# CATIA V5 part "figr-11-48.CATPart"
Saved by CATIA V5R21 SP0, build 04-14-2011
Part number: Part1
Bounding box of the stored display mesh (mm): x -270.607 to 0, y -223.278 to 0, z -13.562 to 46.691
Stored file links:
  D:\CATIA V5R21 E-RESOURCES\CATIA-V5R21\catia-v5r21-prt\c11-catia-v5r21-prt\c11-catia-v5r21-figr-11-48.CATPart
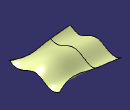
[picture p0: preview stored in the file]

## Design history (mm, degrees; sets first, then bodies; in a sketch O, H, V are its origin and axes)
Set1
  Sweep1: type Unspec, Profile Sketch2, Guide Sketch1
  Extrapol1: ToExtrapol edge of Sweep1, Support Sweep1, Length 100
Body1 (main body)
  Sketch1 on yz-plane, origin (0, 0, 0), H (0, 1, 0), V (0, 0, 1)
    spline S1 through (0, 0) (-40, -10) (-100, 20) (-170, 0) (-220, 10)
    point P1 (0, 0)
    coincidence: P1 O
  Sketch2 on zx-plane, origin (0, 0, 0), H (-1, 0, 0), V (0, 0, 1)
    spline S1 through (0, 0) (60, 30) (121.1814, 19.9844) (171.1814, 9.9844)
    point P1 (0, 0)
    coincidence: P1 O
